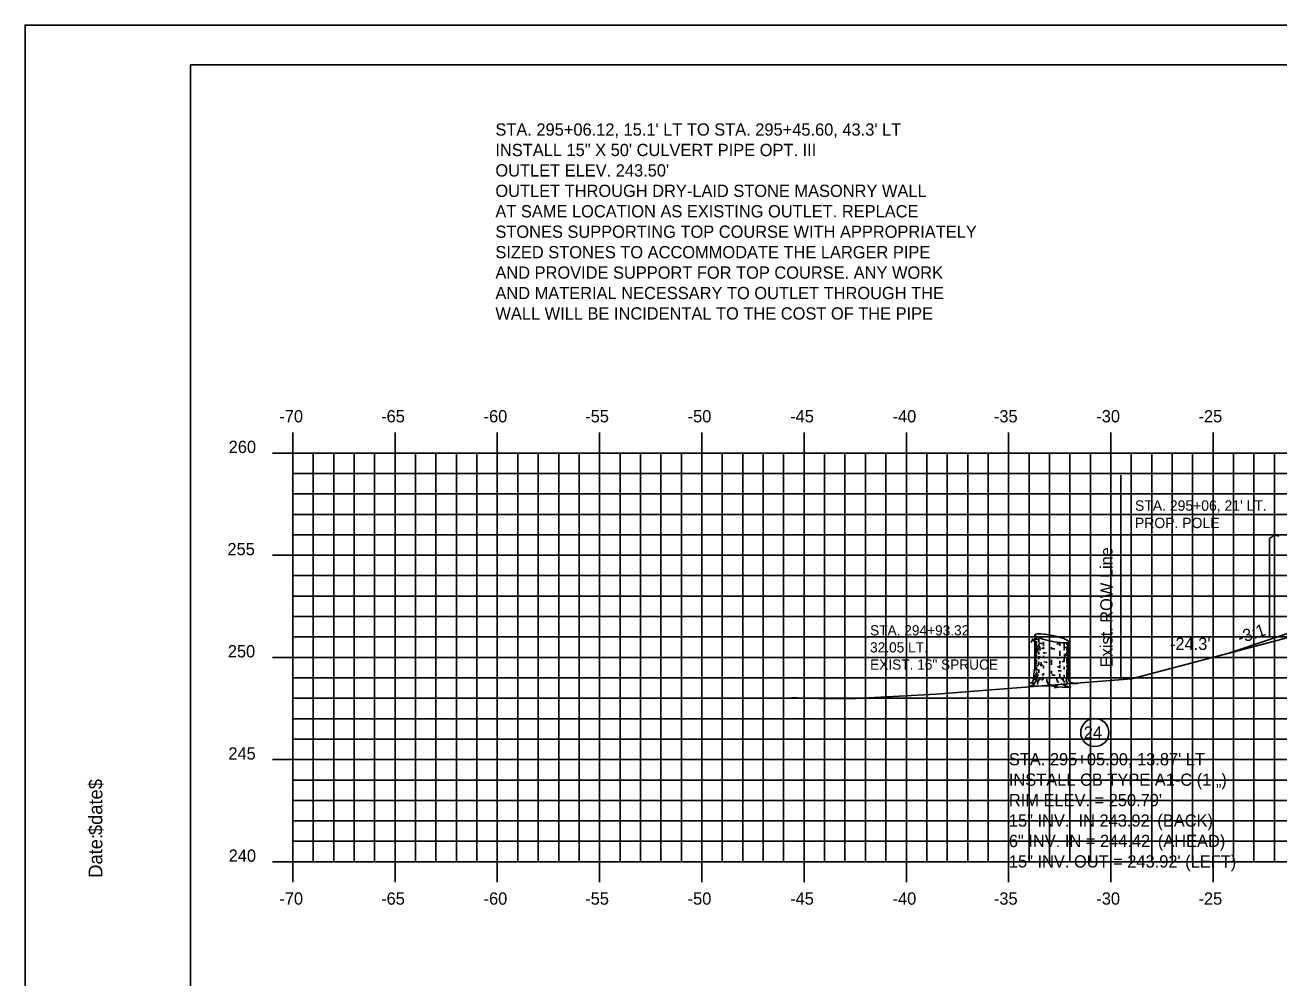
# Model space of a CAD drawing. Extents: x 859352 to 859522, y 366268 to 366378.
# Drawn here: x 859352 to 859413.3, y 366331.6 to 366378.2 of the extents above; entities that cross this region are included whole.
import ezdxf

# ---------------------------------------------------------------- set-up
doc = ezdxf.new("R2010")
doc.units = 0
for name, color, linetype in [('ANNOTATION', 7, 'Continuous'), ('BORDER', 7, 'Continuous'), ('D_Drainage_Text', 7, 'Continuous'), ('D_Roadway_FinishedGrade', 7, 'Continuous'), ('D_Text_Monospaced', 7, 'Continuous'), ('D_Text_Standard', 7, 'Continuous'), ('D_Utilities_Pole_Joint', 7, 'Continuous'), ('D_Utilities_Text', 7, 'Continuous'), ('E_ROW_Line', 7, 'Continuous'), ('H_V ANNOTATION', 7, 'Continuous'), ('JUNK FILL', 7, 'Continuous'), ('MAJOR', 7, 'Continuous'), ('MINOR', 7, 'Continuous'), ('PLOT BOUNDARY', 7, 'Continuous'), ('S_Roadway_Centerline', 7, 'Continuous'), ('S_Trees_Conifer_Pay', 7, 'Continuous')]:
    doc.layers.add(name, color=color, linetype=linetype)

msp = doc.modelspace()

# ---------------------------------------------------------------- linework, layer by layer
at = {"layer": 'BORDER'}
for p, q in [((859520.13, 366376.236), (859360.13, 366376.236)), ((859360.13, 366376.236), (859360.13, 366271.236))]:
    msp.add_line(p, q, dxfattribs=at)
at = {"layer": 'D_Drainage_Text'}
msp.add_circle((859404.342, 366343.56), 0.687, dxfattribs=at)
at = {"layer": 'D_Roadway_FinishedGrade'}
msp.add_lwpolyline([(859415.124, 366348.856), (859410.842, 366347.428)], dxfattribs=at)
at = {"layer": 'D_Utilities_Pole_Joint'}
for p, q in [((859412.879, 366353.048), (859413.036, 366353.159)), ((859412.879, 366348.29), (859412.879, 366353.048))]:
    msp.add_line(p, q, dxfattribs=at)
for start, end in [(90, 125.26439), (54.73561, 90)]:
    msp.add_arc((859413.192, 366352.938), 0.271, start, end, dxfattribs=at)
at = {"layer": 'E_ROW_Line'}
msp.add_line((859405.612, 366346.147), (859405.612, 366356.147), dxfattribs=at)
at = {"layer": 'JUNK FILL'}
msp.add_lwpolyline([(859415.129, 366348.546), (859415.129, 366348.856), (859415.124, 366348.856), (859410.842, 366347.428), (859413.548, 366348.142), (859415.124, 366348.545)], close=True, dxfattribs=at)
at = {"layer": 'MAJOR'}
for p, q in [((859365.129, 366358.238), (859365.129, 366357.236)), ((859370.129, 366358.238), (859370.129, 366357.236)), ((859375.129, 366358.238), (859375.129, 366357.236)), ((859380.129, 366358.238), (859380.129, 366357.236)), ((859385.129, 366358.238), (859385.129, 366357.236)), ((859390.129, 366358.238), (859390.129, 366357.236)), ((859395.129, 366358.238), (859395.129, 366357.236)), ((859400.129, 366358.238), (859400.129, 366357.236)), ((859405.129, 366358.238), (859405.129, 366357.236)), ((859410.129, 366358.238), (859410.129, 366357.236)), ((859364.127, 366357.236), (859365.129, 366357.236)), ((859365.129, 366357.236), (859505.129, 366357.236)), ((859365.129, 366337.236), (859365.129, 366357.236)), ((859365.129, 366337.236), (859365.129, 366357.236)), ((859365.129, 366357.236), (859505.129, 366357.236)), ((859370.129, 366337.236), (859370.129, 366357.236)), ((859375.129, 366337.236), (859375.129, 366357.236)), ((859380.129, 366337.236), (859380.129, 366357.236)), ((859385.129, 366337.236), (859385.129, 366357.236)), ((859390.129, 366337.236), (859390.129, 366357.236)), ((859395.129, 366337.236), (859395.129, 366357.236)), ((859400.129, 366337.236), (859400.129, 366357.236)), ((859405.129, 366337.236), (859405.129, 366357.236)), ((859410.129, 366337.236), (859410.129, 366357.236)), ((859364.127, 366352.236), (859365.129, 366352.236)), ((859365.129, 366352.236), (859505.129, 366352.236)), ((859364.127, 366347.236), (859365.129, 366347.236)), ((859365.129, 366347.236), (859505.129, 366347.236)), ((859364.127, 366342.236), (859365.129, 366342.236)), ((859365.129, 366342.236), (859505.129, 366342.236)), ((859364.127, 366337.236), (859365.129, 366337.236)), ((859365.129, 366337.236), (859505.129, 366337.236)), ((859365.129, 366337.236), (859505.129, 366337.236)), ((859365.129, 366336.234), (859365.129, 366337.236)), ((859370.129, 366336.234), (859370.129, 366337.236)), ((859375.129, 366336.234), (859375.129, 366337.236)), ((859380.129, 366336.234), (859380.129, 366337.236)), ((859385.129, 366336.234), (859385.129, 366337.236)), ((859390.129, 366336.234), (859390.129, 366337.236)), ((859395.129, 366336.234), (859395.129, 366337.236)), ((859400.129, 366336.234), (859400.129, 366337.236)), ((859405.129, 366336.234), (859405.129, 366337.236)), ((859410.129, 366336.234), (859410.129, 366337.236))]:
    msp.add_line(p, q, dxfattribs=at)
at = {"layer": 'MINOR'}
for p, q in [((859366.129, 366337.236), (859366.129, 366357.236)), ((859367.129, 366337.236), (859367.129, 366357.236)), ((859368.129, 366337.236), (859368.129, 366357.236)), ((859369.129, 366337.236), (859369.129, 366357.236)), ((859371.129, 366337.236), (859371.129, 366357.236)), ((859372.129, 366337.236), (859372.129, 366357.236)), ((859373.129, 366337.236), (859373.129, 366357.236)), ((859374.129, 366337.236), (859374.129, 366357.236)), ((859376.129, 366337.236), (859376.129, 366357.236)), ((859377.129, 366337.236), (859377.129, 366357.236)), ((859378.129, 366337.236), (859378.129, 366357.236)), ((859379.129, 366337.236), (859379.129, 366357.236)), ((859381.129, 366337.236), (859381.129, 366357.236)), ((859382.129, 366337.236), (859382.129, 366357.236)), ((859383.129, 366337.236), (859383.129, 366357.236)), ((859384.129, 366337.236), (859384.129, 366357.236)), ((859386.129, 366337.236), (859386.129, 366357.236)), ((859387.129, 366337.236), (859387.129, 366357.236)), ((859388.129, 366337.236), (859388.129, 366357.236)), ((859389.129, 366337.236), (859389.129, 366357.236)), ((859391.129, 366337.236), (859391.129, 366357.236)), ((859392.129, 366337.236), (859392.129, 366357.236)), ((859393.129, 366337.236), (859393.129, 366357.236)), ((859394.129, 366337.236), (859394.129, 366357.236)), ((859396.129, 366337.236), (859396.129, 366357.236)), ((859397.129, 366337.236), (859397.129, 366357.236)), ((859398.129, 366337.236), (859398.129, 366357.236)), ((859399.129, 366337.236), (859399.129, 366357.236)), ((859401.129, 366337.236), (859401.129, 366357.236)), ((859402.129, 366337.236), (859402.129, 366357.236)), ((859403.129, 366337.236), (859403.129, 366357.236)), ((859404.129, 366337.236), (859404.129, 366357.236)), ((859406.129, 366337.236), (859406.129, 366357.236)), ((859407.129, 366337.236), (859407.129, 366357.236)), ((859408.129, 366337.236), (859408.129, 366357.236)), ((859409.129, 366337.236), (859409.129, 366357.236)), ((859411.129, 366337.236), (859411.129, 366357.236)), ((859412.129, 366337.236), (859412.129, 366357.236)), ((859413.129, 366337.236), (859413.129, 366357.236)), ((859365.129, 366356.236), (859505.129, 366356.236)), ((859365.129, 366356.236), (859366.131, 366356.236)), ((859365.129, 366355.236), (859505.129, 366355.236)), ((859365.129, 366355.236), (859366.131, 366355.236)), ((859365.129, 366354.236), (859505.129, 366354.236)), ((859365.129, 366354.236), (859366.131, 366354.236)), ((859365.129, 366353.236), (859505.129, 366353.236)), ((859365.129, 366353.236), (859366.131, 366353.236)), ((859365.129, 366351.236), (859505.129, 366351.236)), ((859365.129, 366351.236), (859366.131, 366351.236)), ((859365.129, 366350.236), (859505.129, 366350.236)), ((859365.129, 366350.236), (859366.131, 366350.236)), ((859365.129, 366349.236), (859505.129, 366349.236)), ((859365.129, 366349.236), (859366.131, 366349.236)), ((859365.129, 366348.236), (859505.129, 366348.236)), ((859365.129, 366348.236), (859366.131, 366348.236)), ((859365.129, 366346.236), (859505.129, 366346.236)), ((859365.129, 366346.236), (859366.131, 366346.236)), ((859365.129, 366345.236), (859505.129, 366345.236)), ((859365.129, 366345.236), (859366.131, 366345.236)), ((859365.129, 366344.236), (859505.129, 366344.236)), ((859365.129, 366344.236), (859366.131, 366344.236)), ((859365.129, 366343.236), (859505.129, 366343.236)), ((859365.129, 366343.236), (859366.131, 366343.236)), ((859365.129, 366341.236), (859505.129, 366341.236)), ((859365.129, 366341.236), (859366.131, 366341.236)), ((859365.129, 366340.236), (859505.129, 366340.236)), ((859365.129, 366340.236), (859366.131, 366340.236)), ((859365.129, 366339.236), (859505.129, 366339.236)), ((859365.129, 366339.236), (859366.131, 366339.236)), ((859365.129, 366339.236), (859505.129, 366339.236)), ((859365.129, 366338.236), (859505.129, 366338.236)), ((859365.129, 366338.236), (859366.131, 366338.236))]:
    msp.add_line(p, q, dxfattribs=at)
at = {"layer": 'PLOT BOUNDARY'}
msp.add_lwpolyline([(859352.036, 366268.177), (859522.036, 366268.177), (859522.036, 366378.177), (859352.036, 366378.177)], close=True, dxfattribs=at)
at = {"layer": 'S_Roadway_Centerline'}
msp.add_lwpolyline([(859389.265, 366345.233), (859389.508, 366345.262), (859389.807, 366345.259), (859390.852, 366345.23), (859392.363, 366345.206), (859396.586, 366345.432), (859406.139, 366346.189), (859413.548, 366348.142)], dxfattribs=at)
at = {"layer": 'S_Trees_Conifer_Pay'}
for p, q in [((859401.416, 366346.686), (859401.416, 366348.333)), ((859401.487, 366348.261), (859401.487, 366348.098)), ((859401.605, 366348.2), (859401.605, 366347.977)), ((859401.487, 366348.031), (859401.487, 366347.903)), ((859401.487, 366347.716), (859401.487, 366347.38)), ((859401.548, 366347.705), (859401.599, 366347.645)), ((859401.605, 366347.888), (859401.605, 366347.841)), ((859401.605, 366347.506), (859401.605, 366347.374)), ((859401.833, 366348.004), (859401.833, 366347.804)), ((859401.833, 366347.747), (859401.833, 366347.658)), ((859402.224, 366347.73), (859402.224, 366347.635)), ((859402.629, 366347.962), (859402.629, 366347.794)), ((859402.629, 366347.557), (859402.629, 366347.32)), ((859402.849, 366347.941), (859402.849, 366347.709)), ((859402.849, 366347.668), (859402.849, 366347.594)), ((859402.974, 366347.949), (859402.974, 366347.852)), ((859402.974, 366347.777), (859402.974, 366347.573)), ((859402.974, 366347.516), (859402.974, 366347.316)), ((859403.033, 366347.96), (859403.033, 366347.489)), ((859403.08, 366346.276), (859403.08, 366347.998)), ((859401.487, 366347.343), (859401.487, 366347.18)), ((859401.487, 366347.133), (859401.487, 366346.916)), ((859401.487, 366346.886), (859401.487, 366346.811)), ((859401.605, 366347.263), (859401.605, 366347.153)), ((859401.605, 366347.018), (859401.605, 366346.876)), ((859401.833, 366347.31), (859401.833, 366347.205)), ((859401.833, 366346.838), (859401.833, 366346.692)), ((859402.224, 366347.117), (859402.224, 366347.042)), ((859402.224, 366347.018), (859402.224, 366346.869)), ((859402.629, 366347.075), (859402.629, 366346.923)), ((859402.629, 366346.88), (859402.629, 366346.707)), ((859402.849, 366347.191), (859402.849, 366347.052)), ((859402.974, 366347.269), (859402.974, 366346.933)), ((859402.974, 366346.88), (859402.974, 366346.744)), ((859403.033, 366347.425), (859403.033, 366347.117)), ((859403.033, 366347.069), (859403.033, 366346.577)), ((859401.487, 366346.771), (859401.487, 366346.598)), ((859401.605, 366346.649), (859401.605, 366346.476)), ((859401.833, 366346.46), (859401.833, 366346.371)), ((859402.224, 366346.577), (859402.224, 366346.424)), ((859402.629, 366346.429), (859402.629, 366346.276)), ((859402.849, 366346.781), (859402.849, 366346.639)), ((859402.849, 366346.377), (859402.849, 366346.283)), ((859402.974, 366346.645), (859402.974, 366346.266)), ((859403.033, 366346.523), (859403.033, 366346.276)), ((859402.412, 366345.819), (859402.538, 366345.883)), ((859402.849, 366345.883), (859402.686, 366345.947))]:
    msp.add_line(p, q, dxfattribs=at)
for points in [[(859401.37, 366348.064), (859401.295, 366348.072), (859401.222, 366347.973)], [(859401.599, 366347.831), (859401.562, 366347.757), (859401.515, 366347.814), (859401.457, 366347.882), (859401.365, 366348.076), (859401.3, 366348.123), (859401.27, 366348.13)], [(859401.585, 366347.578), (859401.548, 366347.705), (859401.484, 366347.821), (859401.453, 366347.888), (859401.384, 366348.035)], [(859401.632, 366347.794), (859401.663, 366347.709), (859401.667, 366347.642), (859401.636, 366347.578)], [(859401.762, 366346.905), (859401.749, 366346.828), (859401.702, 366346.838), (859401.714, 366347.005)], [(859402.901, 366347.304), (859402.907, 366347.399), (859402.863, 366347.376), (859402.863, 366347.281)], [(859401.416, 366346.686), (859401.365, 366346.424), (859401.348, 366346.151), (859401.291, 366346.025), (859401.155, 366345.995), (859401.385, 366345.957), (859401.385, 366345.957), (859401.379, 366345.91), (859401.132, 366345.815), (859401.406, 366345.832), (859401.762, 366345.852), (859402.083, 366345.842), (859402.077, 366345.924), (859402.225, 366345.842), (859402.412, 366345.819), (859402.388, 366345.751), (859402.655, 366345.794), (859402.876, 366345.768), (859403.169, 366345.785), (859402.88, 366345.842), (859402.849, 366345.883), (859403.012, 366345.941), (859403.249, 366345.951), (859403.489, 366345.951), (859403.148, 366346.009), (859403.106, 366346.089), (859403.08, 366346.276)], [(859401.589, 366346.398), (859401.515, 366346.293), (859401.51, 366346.12), (859401.385, 366345.957)], [(859401.49, 366346.544), (859401.484, 366346.398), (859401.437, 366346.33), (859401.426, 366346.13)], [(859401.826, 366346.293), (859401.816, 366346.167), (859401.741, 366346.124)], [(859402.565, 366345.995), (859402.497, 366346.089), (859402.47, 366346.229)], [(859402.791, 366346.235), (859402.791, 366346.103), (859402.88, 366346.004)], [(859402.954, 366346.208), (859402.948, 366346.093), (859403.001, 366346.004), (859403.012, 366345.941)], [(859403.032, 366346.229), (859403.053, 366346.151), (859403.073, 366346.056)], [(859401.548, 366345.904), (859401.562, 366346.042), (859401.636, 366346.171)], [(859402.077, 366345.924), (859402.003, 366346.066), (859401.993, 366346.167)]]:
    msp.add_lwpolyline(points, dxfattribs=at)
for centre, radius, start, end in [((859401.438, 366348.333), 0.0226, 156.59265, 168.2806), ((859401.438, 366348.333), 0.0226, 168.2806, 179.96855), ((859401.442, 366348.333), 0.0264, 179.96855, 190.7806), ((859401.447, 366348.334), 0.0314, 190.7806, 203.48418), ((859401.449, 366348.207), 0.0334, 185.78494, 196.05154), ((859401.449, 366348.052), 0.0334, 185.78494, 196.05154), ((859401.459, 366348.21), 0.0441, 196.05154, 210), ((859401.442, 366348.332), 0.0264, 145.7806, 156.59265), ((859401.467, 366348.343), 0.0527, 203.48418, 213.2806), ((859401.446, 366348.329), 0.0314, 133.07702, 145.7806), ((859401.475, 366348.219), 0.0624, 210, 228.74941), ((859401.491, 366348.359), 0.0817, 213.2806, 227.61132), ((859401.461, 366348.313), 0.0527, 123.2806, 133.07702), ((859401.477, 366348.289), 0.0817, 108.94987, 123.2806), ((859401.548, 366348.302), 0.172, 228.74941, 240), ((859401.605, 366348.483), 0.251, 227.61132, 235.7806), ((859401.531, 366348.13), 0.251, 100.7806, 108.94987), ((859401.915, 366348.939), 0.802, 235.7806, 251.94061), ((859401.634, 366347.588), 0.802, 84.62059, 100.7806), ((859401.747, 366348.647), 0.571, 247.58675, 255.56834), ((859403.272, 366353.101), 5.179, 251.94061, 258.2806), ((859401.224, 366343.23), 5.179, 78.2806, 84.62059), ((859401.224, 366343.23), 5.179, 71.94061, 78.2806), ((859402.581, 366347.392), 0.802, 55.7806, 71.94061), ((859402.891, 366347.848), 0.251, 47.61132, 55.7806), ((859401.449, 366347.609), 0.0334, 185.78494, 196.05154), ((859401.459, 366348.055), 0.0441, 196.05154, 210), ((859401.475, 366348.065), 0.0624, 210, 228.74941), ((859401.548, 366348.147), 0.172, 228.74941, 240), ((859401.747, 366348.492), 0.571, 240, 242.9763), ((859401.747, 366348.048), 0.571, 242.95715, 255.55072), ((859401.747, 366348.492), 0.571, 255.63335, 261.8968), ((859402.248, 366352.01), 4.124, 261.8968, 263.76196), ((859402.249, 366351.777), 4.124, 262.94416, 264.21507), ((859402.248, 366351.566), 4.124, 264.04957, 266.29476), ((859403.272, 366353.101), 5.179, 258.2806, 264.62059), ((859402.249, 366351.777), 4.124, 269.64186, 270), ((859402.249, 366351.777), 4.124, 270, 271.92488), ((859402.248, 366352.01), 4.124, 273.26691, 275.3045), ((859402.861, 366348.743), 0.802, 264.62059, 280.7806), ((859402.75, 366348.259), 0.571, 282.01543, 293.14027), ((859402.749, 366348.048), 0.571, 292.94134, 300), ((859402.964, 366348.201), 0.251, 280.7806, 288.94988), ((859402.75, 366348.259), 0.571, 299.66328, 300), ((859402.949, 366347.914), 0.172, 300, 311.25059), ((859403.019, 366348.042), 0.0817, 288.94988, 303.2806), ((859403.005, 366347.972), 0.0817, 33.2806, 47.61132), ((859403.022, 366347.832), 0.0624, 311.25059, 330), ((859403.035, 366348.017), 0.0527, 303.2806, 313.07702), ((859403.05, 366348.002), 0.0314, 313.07702, 325.7806), ((859403.029, 366347.988), 0.0527, 23.48418, 33.2806), ((859403.054, 366347.999), 0.0264, 325.7806, 336.59265), ((859403.037, 366347.823), 0.0441, 330, 343.94846), ((859403.049, 366347.997), 0.0314, 10.7806, 23.48418), ((859403.057, 366347.998), 0.0226, 336.59265, 348.2806), ((859403.053, 366347.998), 0.0264, 359.96855, 10.7806), ((859403.057, 366347.998), 0.0226, 348.2806, 359.96855), ((859403.048, 366347.82), 0.0334, 0, 16.05154), ((859403.048, 366347.82), 0.0334, 343.94846, 360), ((859401.451, 366347.373), 0.0334, 185.78494, 196.05154), ((859401.451, 366347.163), 0.0334, 185.78494, 196.05154), ((859401.461, 366347.376), 0.0441, 196.05154, 210), ((859401.461, 366347.166), 0.0441, 196.05154, 210), ((859401.477, 366347.385), 0.0624, 210, 228.74941), ((859401.477, 366347.175), 0.0624, 210, 228.74941), ((859401.549, 366347.468), 0.172, 228.74941, 240), ((859401.549, 366347.257), 0.172, 228.74941, 240), ((859401.748, 366347.813), 0.571, 240, 242.81041), ((859401.748, 366347.603), 0.571, 240, 242.81041), ((859401.748, 366347.366), 0.571, 242.81041, 254.60173), ((859401.748, 366347.813), 0.571, 253.07038, 261.8968), ((859402.249, 366351.33), 4.124, 261.8968, 262.38753), ((859402.249, 366351.12), 4.124, 264.54309, 266.85066), ((859402.249, 366351.12), 4.124, 269.64186, 270), ((859402.249, 366351.33), 4.124, 273.33241, 275.91902), ((859402.249, 366351.12), 4.124, 276.85262, 278.1032), ((859402.75, 366347.603), 0.571, 278.1032, 280.72928), ((859402.75, 366347.603), 0.571, 293.14027, 300), ((859402.75, 366347.366), 0.571, 293.14027, 300), ((859402.75, 366347.813), 0.571, 299.66328, 300), ((859402.949, 366347.468), 0.172, 300, 311.25059), ((859402.949, 366347.257), 0.172, 300, 311.25059), ((859402.949, 366347.021), 0.172, 300, 311.25059), ((859403.022, 366347.385), 0.0624, 311.25059, 330), ((859403.022, 366347.175), 0.0624, 311.25059, 330), ((859403.022, 366346.938), 0.0624, 311.25059, 330), ((859403.037, 366347.376), 0.0441, 330, 343.94846), ((859403.037, 366347.166), 0.0441, 330, 343.94846), ((859403.037, 366346.929), 0.0441, 330, 343.94846), ((859403.048, 366347.373), 0.0334, 0, 16.05154), ((859403.048, 366347.373), 0.0334, 343.94846, 360), ((859403.048, 366347.163), 0.0334, 0, 16.05154), ((859403.048, 366347.163), 0.0334, 343.94846, 360), ((859403.048, 366346.926), 0.0334, 0, 16.05154), ((859403.048, 366346.926), 0.0334, 343.94846, 360), ((859401.451, 366346.728), 0.0334, 185.78494, 196.05154), ((859401.451, 366346.312), 0.0334, 185.78494, 196.05154), ((859401.461, 366346.731), 0.0441, 196.05154, 210), ((859401.461, 366346.315), 0.0441, 196.05154, 210), ((859401.477, 366346.74), 0.0624, 210, 228.74941), ((859401.477, 366346.325), 0.0624, 210, 228.74941), ((859401.549, 366346.823), 0.172, 228.74941, 240), ((859401.549, 366346.407), 0.172, 228.74941, 240), ((859401.748, 366347.168), 0.571, 240, 250.70928), ((859401.748, 366346.973), 0.571, 242.72792, 251.49327), ((859402.249, 366350.49), 4.124, 263.21039, 264.21507), ((859402.249, 366350.49), 4.124, 269.86721, 270), ((859402.249, 366350.49), 4.124, 270, 272.18834), ((859402.249, 366350.883), 4.124, 273.68066, 275.28397), ((859402.249, 366350.686), 4.124, 274.16025, 276.50094), ((859402.761, 366347.174), 0.571, 291.97323, 298.76314), ((859402.75, 366346.973), 0.571, 293.14027, 300), ((859402.75, 366346.752), 0.571, 295.46862, 300), ((859402.949, 366346.627), 0.172, 300, 311.25059), ((859402.949, 366346.407), 0.172, 300, 311.25059), ((859403.022, 366346.545), 0.0624, 311.25059, 330), ((859403.022, 366346.325), 0.0624, 311.25059, 330), ((859403.037, 366346.536), 0.0441, 330, 343.94846), ((859403.037, 366346.315), 0.0441, 330, 343.94846), ((859403.048, 366346.728), 0.0334, 0, 16.05154), ((859403.048, 366346.533), 0.0334, 0, 16.05154), ((859403.048, 366346.533), 0.0334, 343.94846, 360), ((859403.048, 366346.312), 0.0334, 0, 16.05154), ((859403.048, 366346.312), 0.0334, 343.94846, 360), ((859401.748, 366346.752), 0.571, 258.36297, 261.8968), ((859402.249, 366350.27), 4.124, 261.8968, 262.63158), ((859402.249, 366350.27), 4.124, 276.48798, 277.55621)]:
    msp.add_arc(centre, radius, start, end, dxfattribs=at)

# ---------------------------------------------------------------- texts
at = {"layer": 'ANNOTATION'}
msp.add_text('-3:1', height=0.6, rotation=18.43495, dxfattribs=at).set_placement((859411.441, 366347.899))
at = {"layer": 'BORDER'}
for s, p in [('$date$', (859355.815, 366338.542)), ('Date:', (859355.815, 366336.453))]:
    msp.add_text(s, height=0.6696, rotation=90, dxfattribs=at).set_placement(p)
at = {"layer": 'D_Drainage_Text'}
for s, p in [("STA. 295+06.12, 15.1' LT TO STA. 295+45.60, 43.3' LT", (859375.035, 366372.766)), ('INSTALL 15" X 50\' CULVERT PIPE OPT. III', (859375.035, 366371.766)), ("OUTLET ELEV. 243.50'", (859375.035, 366370.766)), ('OUTLET THROUGH DRY-LAID STONE MASONRY WALL', (859375.035, 366369.766)), ('AT SAME LOCATION AS EXISTING OUTLET. REPLACE', (859375.035, 366368.766)), ('STONES SUPPORTING TOP COURSE WITH APPROPRIATELY', (859375.035, 366367.766)), ('SIZED STONES TO ACCOMMODATE THE LARGER PIPE', (859375.035, 366366.766)), ('AND PROVIDE SUPPORT FOR TOP COURSE. ANY WORK', (859375.035, 366365.766)), ('AND MATERIAL NECESSARY TO OUTLET THROUGH THE', (859375.035, 366364.766)), ('WALL WILL BE INCIDENTAL TO THE COST OF THE PIPE', (859375.035, 366363.766)), ("STA. 295+05.00, 13.87' LT", (859400.143, 366341.954)), ('INSTALL CB TYPE A1-C (1 „)', (859400.143, 366340.954)), ("RIM ELEV. = 250.79'", (859400.143, 366339.954)), ('15" INV.  IN 243.92\' (BACK)', (859400.143, 366338.954)), ('6" INV. IN = 244.42\' (AHEAD)', (859400.143, 366337.954)), ('15" INV. OUT = 243.92\' (LEFT)', (859400.143, 366336.954))]:
    msp.add_text(s, height=0.6, dxfattribs=at).set_placement(p)
at = {"layer": 'D_Text_Monospaced'}
for s, height, p in [('STA. 294+93.32', 0.49998, (859393.356, 366348.311)), ('32.05 LT.', 0.5, (859393.356, 366347.477)), ('EXIST. 16" SPRUCE', 0.49998, (859393.356, 366346.637))]:
    msp.add_text(s, height=height, dxfattribs=at).set_placement(p)
at = {"layer": 'D_Text_Standard'}
msp.add_text("-24.3'", height=0.6, dxfattribs=at).set_placement((859408.019, 366347.6))
at = {"layer": 'D_Utilities_Text'}
for s, p in [("STA. 295+06, 21' LT.", (859406.31, 366354.411)), ('PROP. POLE', (859406.31, 366353.561))]:
    msp.add_text(s, height=0.51, dxfattribs=at).set_placement(p)
at = {"layer": 'E_ROW_Line'}
msp.add_text('Exist. ROW Line', height=0.6, rotation=90, dxfattribs=at).set_placement((859405.212, 366346.747))
at = {"layer": 'H_V ANNOTATION'}
for s, p in [('-70', (859364.471, 366358.736)), ('-65', (859369.447, 366358.736)), ('-60', (859374.455, 366358.736)), ('-55', (859379.426, 366358.736)), ('-50', (859384.434, 366358.736)), ('-45', (859389.447, 366358.736)), ('-40', (859394.455, 366358.736)), ('-35', (859399.41, 366358.736)), ('-30', (859404.418, 366358.736)), ('-25', (859409.415, 366358.736)), ('260', (859361.992, 366357.236)), ('255', (859361.933, 366352.236)), ('250', (859361.949, 366347.236)), ('24', (859403.806, 366343.256)), ('245', (859361.976, 366342.236)), ('240', (859361.992, 366337.236)), ('-70', (859364.471, 366335.136)), ('-65', (859369.447, 366335.136)), ('-60', (859374.455, 366335.136)), ('-55', (859379.426, 366335.136)), ('-50', (859384.434, 366335.136)), ('-45', (859389.447, 366335.136)), ('-40', (859394.455, 366335.136)), ('-35', (859399.41, 366335.136)), ('-30', (859404.418, 366335.136)), ('-25', (859409.415, 366335.136))]:
    msp.add_text(s, height=0.6, dxfattribs=at).set_placement(p)

doc.saveas('drawing.dxf')
